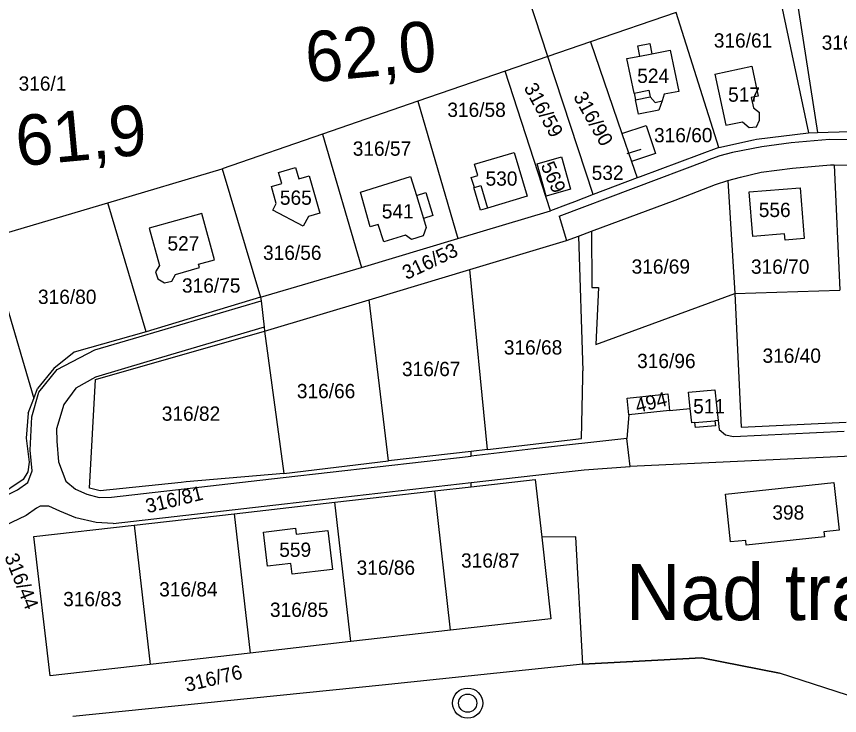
# Model space of a CAD drawing. Extents: x -805826 to -803822, y -1165880 to -1164382.
# Drawn here: x -805597.3 to -805401.4, y -1164887.3 to -1164720.9 of the extents above; entities that cross this region are included whole.
import ezdxf

# ---------------------------------------------------------------- set-up
doc = ezdxf.new("R2010")
doc.units = 0
for name, color, linetype in [('kilometráž - 2880', 7, 'Continuous'), ('kn_celek - Cisla parcel pomocna', 7, 'Continuous'), ('kn_celek - Cisla pozemkovych parcel', 7, 'Continuous'), ('kn_celek - Cisla stavebnich parcel', 7, 'Continuous'), ('kn_celek - Dalsi prvky mapy popis', 7, 'Continuous'), ('kn_celek - Hranice parcel', 7, 'Continuous'), ('kn_celek - Vnitrni kresby', 7, 'Continuous'), ('plochy - SZDC', 7, 'Continuous')]:
    doc.layers.add(name, color=color, linetype=linetype)

msp = doc.modelspace()

# ---------------------------------------------------------------- linework, layer by layer
at = {"layer": 'kilometráž - 2880'}
for radius in [3.59, 2.17]:
    msp.add_circle((-805489.96, -1164884.32), radius, dxfattribs=at)
at = {"layer": 'kn_celek - Cisla parcel pomocna'}
msp.add_line((-805448.76, -1164752.55), (-805452.11, -1164753.57), dxfattribs=at)
at = {"layer": 'kn_celek - Hranice parcel'}
for p, q in [((-805416.61, -1164711.68), (-805408.85, -1164748.58)), ((-805412.4, -1164711.49), (-805406.69, -1164748.5)), ((-805470.84, -1164730.39), (-805476.69, -1164712.54)), ((-805440.33, -1164719.92), (-805460.68, -1164726.9)), ((-805430.19, -1164752.06), (-805440.33, -1164719.92)), ((-805460.68, -1164726.9), (-805470.84, -1164730.39)), ((-805460.68, -1164726.9), (-805453.24, -1164748.73)), ((-805449.44, -1164727.87), (-805446.59, -1164727.32)), ((-805448.96, -1164730.29), (-805449.44, -1164727.87)), ((-805446.59, -1164727.32), (-805446.13, -1164729.74)), ((-805446.13, -1164729.74), (-805441.77, -1164728.9)), ((-805441.77, -1164728.9), (-805439.69, -1164738.68)), ((-805470.84, -1164730.39), (-805481.02, -1164733.9)), ((-805460.07, -1164763.25), (-805470.84, -1164730.39)), ((-805452.08, -1164730.89), (-805448.96, -1164730.29)), ((-805450.33, -1164739.12), (-805452.08, -1164730.89)), ((-805431.14, -1164734.58), (-805422.33, -1164732.66)), ((-805422.33, -1164732.66), (-805420.78, -1164739.8)), ((-805481.02, -1164733.9), (-805501.84, -1164741.04)), ((-805470.22, -1164767.14), (-805481.02, -1164733.9)), ((-805431.14, -1164734.58), (-805428.49, -1164746.77)), ((-805450.33, -1164739.12), (-805449.97, -1164740.67)), ((-805443.15, -1164739.38), (-805443.69, -1164740.97)), ((-805439.69, -1164738.68), (-805443.15, -1164739.38)), ((-805501.84, -1164741.04), (-805524.52, -1164748.85)), ((-805501.84, -1164741.04), (-805492.26, -1164773.73)), ((-805449.26, -1164744.09), (-805449.97, -1164740.67)), ((-805443.69, -1164740.97), (-805444.47, -1164743.17)), ((-805420.78, -1164739.8), (-805422.45, -1164740.16)), ((-805422.45, -1164740.16), (-805421.92, -1164742.61)), ((-805444.47, -1164743.17), (-805449.26, -1164744.09)), ((-805421.92, -1164742.61), (-805420.49, -1164743.71)), ((-805421.19, -1164747.14), (-805420.48, -1164745.54)), ((-805420.48, -1164745.54), (-805420.49, -1164743.71)), ((-805453.24, -1164748.73), (-805447.49, -1164746.83)), ((-805447.49, -1164746.83), (-805445.28, -1164753.47)), ((-805428.49, -1164746.77), (-805424.53, -1164745.97)), ((-805424.53, -1164745.97), (-805422.96, -1164747.27)), ((-805422.96, -1164747.27), (-805421.19, -1164747.14)), ((-805524.52, -1164748.85), (-805548.34, -1164757.09)), ((-805524.52, -1164748.85), (-805515.24, -1164780.59)), ((-805453.24, -1164748.73), (-805450.98, -1164755.36)), ((-805421.18, -1164750.08), (-805408.85, -1164748.58)), ((-805408.85, -1164748.58), (-805406.69, -1164748.5)), ((-805406.69, -1164748.5), (-805398.97, -1164748.23)), ((-805430.19, -1164752.06), (-805421.93, -1164750.23)), ((-805421.93, -1164750.23), (-805421.18, -1164750.08)), ((-805412.93, -1164750.97), (-805419.97, -1164751.89)), ((-805403.85, -1164750.15), (-805412.93, -1164750.97)), ((-805398.74, -1164750.19), (-805403.85, -1164750.15)), ((-805488.36, -1164756.04), (-805478.91, -1164753.21)), ((-805478.91, -1164753.21), (-805475.77, -1164763.65)), ((-805430.19, -1164752.06), (-805448.92, -1164759)), ((-805426.96, -1164753.24), (-805429.9, -1164754.04)), ((-805419.97, -1164751.89), (-805426.96, -1164753.24)), ((-805473.43, -1164755.93), (-805467.65, -1164754.27)), ((-805468.15, -1164768.4), (-805432.78, -1164755.06)), ((-805467.65, -1164754.27), (-805465.46, -1164761.98)), ((-805445.28, -1164753.47), (-805450.98, -1164755.36)), ((-805429.9, -1164754.04), (-805432.78, -1164755.06)), ((-805575.61, -1164765.21), (-805548.34, -1164757.09)), ((-805548.34, -1164757.09), (-805539.22, -1164787.71)), ((-805534.98, -1164757.98), (-805530.93, -1164756.81)), ((-805530.93, -1164756.81), (-805530.16, -1164759.48)), ((-805487.56, -1164758.75), (-805488.36, -1164756.04)), ((-805471.23, -1164763.63), (-805473.43, -1164755.93)), ((-805450.98, -1164755.36), (-805449.65, -1164759.26)), ((-805420.07, -1164757.92), (-805412.65, -1164757)), ((-805412.65, -1164757), (-805403.6, -1164756.17)), ((-805403.6, -1164756.17), (-805402.75, -1164756.18)), ((-805402.75, -1164756.18), (-805398.55, -1164756.29)), ((-805402.75, -1164756.18), (-805401.35, -1164786.02)), ((-805534.2, -1164760.64), (-805534.98, -1164757.98)), ((-805530.16, -1164759.48), (-805527.71, -1164758.78)), ((-805527.71, -1164758.78), (-805525.15, -1164767.7)), ((-805515.49, -1164762.68), (-805503.54, -1164758.93)), ((-805503.54, -1164758.93), (-805502.16, -1164763.45)), ((-805489.1, -1164759.2), (-805487.56, -1164758.75)), ((-805488.36, -1164761.57), (-805489.1, -1164759.2)), ((-805449.65, -1164759.26), (-805460.07, -1164763.25)), ((-805448.92, -1164759), (-805449.65, -1164759.26)), ((-805428.01, -1164759.91), (-805425, -1164759.11)), ((-805425, -1164759.11), (-805420.07, -1164757.92)), ((-805536.65, -1164761.34), (-805534.2, -1164760.64)), ((-805433.83, -1164761.97), (-805430.96, -1164760.88)), ((-805430.96, -1164760.88), (-805428.01, -1164759.91)), ((-805428.01, -1164759.91), (-805426.34, -1164786.82)), ((-805535.49, -1164765.38), (-805536.65, -1164761.34)), ((-805513.12, -1164770.95), (-805515.49, -1164762.68)), ((-805502.16, -1164763.45), (-805499.87, -1164762.74)), ((-805499.87, -1164762.74), (-805498.28, -1164768.26)), ((-805488.48, -1164761.6), (-805488.36, -1164761.57)), ((-805486.88, -1164766.95), (-805488.48, -1164761.6)), ((-805465.46, -1164761.98), (-805471.23, -1164763.63)), ((-805440.6, -1164764.55), (-805436.72, -1164763.1)), ((-805436.72, -1164763.1), (-805433.83, -1164761.97)), ((-805422.94, -1164762.62), (-805410.81, -1164761.63)), ((-805422.07, -1164773.22), (-805422.94, -1164762.62)), ((-805410.81, -1164761.63), (-805409.85, -1164773.75)), ((-805475.77, -1164763.65), (-805485.25, -1164766.46)), ((-805464.51, -1164764.95), (-805466.03, -1164765.53)), ((-805460.07, -1164763.25), (-805464.51, -1164764.95)), ((-805460.52, -1164771.98), (-805440.6, -1164764.55)), ((-805604.38, -1164773.78), (-805575.61, -1164765.21)), ((-805566.47, -1164795.9), (-805575.61, -1164765.21)), ((-805536.34, -1164766.94), (-805535.49, -1164765.38)), ((-805529.1, -1164770.75), (-805536.34, -1164766.94)), ((-805485.25, -1164766.46), (-805486.88, -1164766.95)), ((-805466.03, -1164765.53), (-805470.22, -1164767.14)), ((-805553.23, -1164767.75), (-805565.77, -1164771.25)), ((-805550.17, -1164778.77), (-805553.23, -1164767.75)), ((-805527.87, -1164768.49), (-805529.1, -1164770.75)), ((-805525.15, -1164767.7), (-805527.87, -1164768.49)), ((-805498.28, -1164768.26), (-805500.47, -1164768.94)), ((-805500.47, -1164768.94), (-805499.8, -1164771.12)), ((-805492.26, -1164773.73), (-805470.22, -1164767.14)), ((-805468.15, -1164768.4), (-805466.43, -1164774.19)), ((-805511.22, -1164770.38), (-805513.12, -1164770.95)), ((-805509.93, -1164774.52), (-805511.22, -1164770.38)), ((-805565.77, -1164771.25), (-805563.3, -1164780.13)), ((-805504.75, -1164772.9), (-805509.93, -1164774.52)), ((-805503.3, -1164773.95), (-805504.75, -1164772.9)), ((-805499.8, -1164771.12), (-805500.57, -1164773.09)), ((-805463.61, -1164773.14), (-805460.52, -1164771.98)), ((-805460.52, -1164771.98), (-805460.37, -1164784.97)), ((-805414.52, -1164772.62), (-805422.07, -1164773.22)), ((-805414.39, -1164774.11), (-805414.52, -1164772.62)), ((-805604.38, -1164773.78), (-805593.22, -1164811.82)), ((-805515.24, -1164780.59), (-805492.26, -1164773.73)), ((-805500.57, -1164773.09), (-805503.3, -1164773.95)), ((-805489.44, -1164781.07), (-805466.43, -1164774.19)), ((-805466.43, -1164774.19), (-805463.61, -1164773.14)), ((-805463.61, -1164773.14), (-805462.53, -1164805.18)), ((-805409.85, -1164773.75), (-805414.39, -1164774.11)), ((-805554.04, -1164779.84), (-805550.17, -1164778.77)), ((-805563.3, -1164780.13), (-805564.26, -1164781.62)), ((-805559.52, -1164782.26), (-805553.81, -1164780.65)), ((-805553.81, -1164780.65), (-805554.04, -1164779.84)), ((-805539.22, -1164787.71), (-805515.24, -1164780.59)), ((-805564.26, -1164781.62), (-805563.7, -1164783.35)), ((-805560.38, -1164783.84), (-805559.52, -1164782.26)), ((-805513.36, -1164788.3), (-805489.44, -1164781.07)), ((-805485.2, -1164823.93), (-805489.44, -1164781.07)), ((-805563.7, -1164783.35), (-805562.14, -1164784.24)), ((-805562.14, -1164784.24), (-805560.38, -1164783.84)), ((-805460.37, -1164784.97), (-805460.37, -1164785.38)), ((-805460.37, -1164785.38), (-805458.81, -1164785.4)), ((-805458.81, -1164785.4), (-805459.43, -1164798.91)), ((-805426.34, -1164786.82), (-805401.35, -1164786.02)), ((-805539.22, -1164787.71), (-805566.47, -1164795.9)), ((-805539.22, -1164787.71), (-805539.12, -1164788.58)), ((-805539.12, -1164788.58), (-805538.38, -1164794.81)), ((-805538.27, -1164795.8), (-805513.36, -1164788.3)), ((-805508.83, -1164826.67), (-805513.36, -1164788.3)), ((-805459.43, -1164798.91), (-805426.34, -1164786.82)), ((-805426.34, -1164786.82), (-805424.87, -1164818.65)), ((-805566.47, -1164795.9), (-805583.61, -1164800.8)), ((-805578.54, -1164807.27), (-805538.27, -1164795.8)), ((-805538.38, -1164794.81), (-805538.27, -1164795.8)), ((-805538.27, -1164795.8), (-805533.7, -1164829.62)), ((-805583.61, -1164800.8), (-805588.43, -1164804.66)), ((-805588.43, -1164804.66), (-805592.31, -1164809.45)), ((-805462.56, -1164806.78), (-805462.53, -1164805.18)), ((-805579.93, -1164833.18), (-805578.54, -1164807.27)), ((-805462.88, -1164821.36), (-805462.56, -1164806.78)), ((-805593.22, -1164811.82), (-805592.31, -1164809.45)), ((-805437.4, -1164810.31), (-805431.13, -1164809.74)), ((-805431.13, -1164809.74), (-805430.33, -1164817)), ((-805594.53, -1164815.28), (-805593.22, -1164811.82)), ((-805452.01, -1164811.73), (-805442.32, -1164810.72)), ((-805451.63, -1164815.7), (-805452.01, -1164811.73)), ((-805442.32, -1164810.72), (-805441.91, -1164814.69)), ((-805436.99, -1164814.18), (-805437.4, -1164810.31)), ((-805594.53, -1164815.28), (-805595.06, -1164821.26)), ((-805451.63, -1164815.7), (-805452.05, -1164821.31)), ((-805441.91, -1164814.69), (-805451.63, -1164815.7)), ((-805441.91, -1164814.69), (-805436.99, -1164814.18)), ((-805436.63, -1164817.61), (-805436.99, -1164814.18)), ((-805435.86, -1164817.54), (-805436.63, -1164817.61)), ((-805435.72, -1164818.72), (-805435.86, -1164817.54)), ((-805430.33, -1164817), (-805431.09, -1164817.08)), ((-805431.09, -1164817.08), (-805430.95, -1164818.29)), ((-805430.33, -1164817), (-805430.08, -1164819.17)), ((-805424.87, -1164818.65), (-805399.9, -1164817.43)), ((-805430.95, -1164818.29), (-805435.72, -1164818.72)), ((-805430.08, -1164819.17), (-805428.62, -1164820.47)), ((-805426.66, -1164820.85), (-805400.32, -1164819.59)), ((-805595.06, -1164821.26), (-805594.34, -1164826.99)), ((-805485.2, -1164823.93), (-805462.88, -1164821.36)), ((-805452.05, -1164821.31), (-805474.31, -1164823.82)), ((-805451.24, -1164827.98), (-805452.05, -1164821.31)), ((-805428.62, -1164820.47), (-805426.66, -1164820.85)), ((-805474.31, -1164823.82), (-805489.13, -1164825.51)), ((-805489.13, -1164824.38), (-805508.83, -1164826.67)), ((-805485.2, -1164823.93), (-805489.13, -1164824.38)), ((-805489.13, -1164825.51), (-805489.13, -1164824.38)), ((-805387.37, -1164825.01), (-805451.24, -1164827.98)), ((-805594.34, -1164826.99), (-805594.59, -1164829.23)), ((-805533.7, -1164829.62), (-805508.83, -1164826.67)), ((-805594.59, -1164829.23), (-805595.74, -1164831.06)), ((-805533.7, -1164829.62), (-805556.93, -1164831.67)), ((-805473.7, -1164830.04), (-805462.19, -1164828.76)), ((-805462.19, -1164828.76), (-805451.24, -1164827.98)), ((-805595.74, -1164831.06), (-805603.81, -1164836.55)), ((-805556.93, -1164831.67), (-805558.14, -1164831.8)), ((-805489.12, -1164831.81), (-805473.7, -1164830.04)), ((-805489.12, -1164832.82), (-805473.9, -1164831.06)), ((-805473.9, -1164831.06), (-805472.33, -1164844.82)), ((-805577.38, -1164833.81), (-805579.93, -1164833.18)), ((-805558.14, -1164831.8), (-805577.38, -1164833.81)), ((-805533.58, -1164836.89), (-805489.12, -1164831.81)), ((-805497.76, -1164833.82), (-805489.12, -1164832.82)), ((-805489.12, -1164832.82), (-805489.12, -1164831.81)), ((-805428.57, -1164834.57), (-805402.84, -1164831.8)), ((-805402.84, -1164831.8), (-805401.53, -1164843.13)), ((-805521.58, -1164836.51), (-805497.76, -1164833.82)), ((-805494, -1164866.97), (-805497.76, -1164833.82)), ((-805427.38, -1164845.91), (-805428.57, -1164834.57)), ((-805591.68, -1164837.46), (-805592.55, -1164837.88)), ((-805589.65, -1164837.41), (-805591.68, -1164837.46)), ((-805587, -1164838.65), (-805589.65, -1164837.41)), ((-805574.34, -1164841.56), (-805533.58, -1164836.89)), ((-805545.49, -1164839.24), (-805521.58, -1164836.51)), ((-805517.73, -1164869.63), (-805521.58, -1164836.51)), ((-805592.55, -1164837.88), (-805595.02, -1164839.63)), ((-805583.24, -1164840.2), (-805587, -1164838.65)), ((-805569.35, -1164841.95), (-805545.49, -1164839.24)), ((-805545.49, -1164839.24), (-805541.69, -1164872.4)), ((-805595.02, -1164839.63), (-805602.1, -1164843.02)), ((-805578.39, -1164841.35), (-805583.24, -1164840.2)), ((-805574.34, -1164841.56), (-805578.39, -1164841.35)), ((-805593.16, -1164844.68), (-805569.35, -1164841.95)), ((-805569.35, -1164841.95), (-805565.55, -1164875.1)), ((-805538.51, -1164843.59), (-805530.92, -1164842.7)), ((-805530.92, -1164842.7), (-805530.76, -1164844.1)), ((-805530.76, -1164844.1), (-805523.23, -1164843.2)), ((-805523.23, -1164843.2), (-805522.13, -1164852.49)), ((-805401.53, -1164843.13), (-805405.15, -1164843.52)), ((-805589.35, -1164877.84), (-805593.16, -1164844.68)), ((-805537.55, -1164851.72), (-805538.51, -1164843.59)), ((-805464.19, -1164844.7), (-805472.33, -1164844.82)), ((-805472.33, -1164844.82), (-805470.12, -1164864.24)), ((-805462.52, -1164875.08), (-805464.19, -1164844.7)), ((-805405.03, -1164844.71), (-805423.65, -1164846.74)), ((-805405.15, -1164843.52), (-805405.03, -1164844.71)), ((-805423.79, -1164845.57), (-805427.38, -1164845.91)), ((-805423.65, -1164846.74), (-805423.79, -1164845.57)), ((-805532.02, -1164851.07), (-805537.55, -1164851.72)), ((-805531.7, -1164853.65), (-805532.02, -1164851.07)), ((-805522.13, -1164852.49), (-805531.7, -1164853.65)), ((-805470.12, -1164864.24), (-805494, -1164866.97)), ((-805494, -1164866.97), (-805517.73, -1164869.63)), ((-805517.73, -1164869.63), (-805541.69, -1164872.4)), ((-805541.69, -1164872.4), (-805565.55, -1164875.1)), ((-805462.52, -1164875.08), (-805434.29, -1164873.57)), ((-805434.29, -1164873.57), (-805415.73, -1164877.21)), ((-805565.55, -1164875.1), (-805589.35, -1164877.84)), ((-805462.52, -1164875.08), (-805510.27, -1164880.08)), ((-805384.69, -1164887.2), (-805415.73, -1164877.21)), ((-805510.27, -1164880.08), (-805583.88, -1164887.5))]:
    msp.add_line(p, q, dxfattribs=at)
at = {"layer": 'kn_celek - Vnitrni kresby'}
for p, q in [((-805448.96, -1164730.29), (-805446.13, -1164729.74)), ((-805450.33, -1164739.12), (-805446.84, -1164738.38)), ((-805446.84, -1164738.38), (-805446.51, -1164740)), ((-805449.97, -1164740.67), (-805446.51, -1164740)), ((-805446.51, -1164740), (-805445.36, -1164741.32)), ((-805445.36, -1164741.32), (-805443.69, -1164740.97)), ((-805488.36, -1164761.57), (-805486.85, -1164761.12)), ((-805486.85, -1164761.12), (-805485.25, -1164766.46)), ((-805502.16, -1164763.45), (-805500.47, -1164768.94)), ((-805568.15, -1164797.12), (-805539.12, -1164788.58)), ((-805538.38, -1164794.81), (-805566.33, -1164803.07)), ((-805578.67, -1164800.25), (-805568.15, -1164797.12)), ((-805587.68, -1164804.92), (-805578.67, -1164800.25)), ((-805566.33, -1164803.07), (-805578.52, -1164806.74)), ((-805591.98, -1164810.31), (-805587.68, -1164804.92)), ((-805578.52, -1164806.74), (-805583.17, -1164809.31)), ((-805583.17, -1164809.31), (-805586.04, -1164813.21)), ((-805593.67, -1164816.2), (-805591.98, -1164810.31)), ((-805586.04, -1164813.21), (-805587.8, -1164819.01)), ((-805594.07, -1164824.13), (-805593.67, -1164816.2)), ((-805435.86, -1164817.54), (-805431.09, -1164817.08)), ((-805587.8, -1164819.01), (-805587.76, -1164821.93)), ((-805587.76, -1164821.93), (-805587.34, -1164826.9)), ((-805593.6, -1164829.06), (-805594.07, -1164824.13)), ((-805533.88, -1164830.58), (-805489.13, -1164825.51)), ((-805587.34, -1164826.9), (-805585.58, -1164831.46)), ((-805594.65, -1164831.81), (-805593.6, -1164829.06)), ((-805585.58, -1164831.46), (-805583.3, -1164833.4)), ((-805574.68, -1164835.3), (-805533.88, -1164830.58)), ((-805602.11, -1164836.05), (-805597.07, -1164833.55)), ((-805597.07, -1164833.55), (-805594.65, -1164831.81)), ((-805583.3, -1164833.4), (-805580.55, -1164834.54)), ((-805580.55, -1164834.54), (-805577.69, -1164835.33)), ((-805577.69, -1164835.33), (-805574.68, -1164835.3))]:
    msp.add_line(p, q, dxfattribs=at)
at = {"layer": 'plochy - SZDC'}
for p, q in [((-805434.29, -1164873.57), (-805462.52, -1164875.08)), ((-805415.73, -1164877.21), (-805434.29, -1164873.57)), ((-805462.52, -1164875.08), (-805510.27, -1164880.08)), ((-805384.69, -1164887.2), (-805415.73, -1164877.21)), ((-805510.27, -1164880.08), (-805583.88, -1164887.5))]:
    msp.add_line(p, q, dxfattribs=at)

# ---------------------------------------------------------------- texts
at = {"layer": 'kilometráž - 2880'}
for s, rotation, p in [('62,0', 5.3684, (-805528.04, -1164736.63)), ('61,9', 5.3097, (-805597.01, -1164756.54))]:
    msp.add_text(s, height=12, rotation=rotation, dxfattribs=at).set_placement(p)
at = {"layer": 'kn_celek - Cisla parcel pomocna'}
msp.add_text('532', height=3.4, dxfattribs=at).set_placement((-805460.44, -1164759.77))
msp.add_text('316/44', height=3.4, rotation=291.807, dxfattribs=at).set_placement((-805600.26, -1164849.46))
at = {"layer": 'kn_celek - Cisla pozemkovych parcel'}
for s, p in [('316/61', (-805431.37, -1164728.27)), ('316/62', (-805405.69, -1164728.77)), ('316/1', (-805596.83, -1164738.52)), ('316/58', (-805494.79, -1164744.77)), ('316/60', (-805445.6, -1164750.81)), ('316/57', (-805517.3, -1164754.01)), ('316/56', (-805538.65, -1164778.8)), ('316/69', (-805450.94, -1164782.08)), ('316/70', (-805422.53, -1164782.11)), ('316/75', (-805557.94, -1164786.6)), ('316/80', (-805592.21, -1164789.29)), ('316/68', (-805481.34, -1164801.33)), ('316/40', (-805419.78, -1164803.3)), ('316/96', (-805449.62, -1164804.56)), ('316/67', (-805505.58, -1164806.47)), ('316/66', (-805530.6, -1164811.73)), ('316/82', (-805562.75, -1164817.1)), ('316/87', (-805491.52, -1164852.07)), ('316/86', (-805516.38, -1164853.76)), ('316/84', (-805563.37, -1164858.92)), ('316/83', (-805586.22, -1164861.24)), ('316/85', (-805537.01, -1164863.79))]:
    msp.add_text(s, height=3.4, dxfattribs=at).set_placement(p)
for s, rotation, p in [('316/59', 298.566, (-805476.69, -1164737.79)), ('316/90', 299.259, (-805464.92, -1164739.93)), ('316/53', 25.326, (-805504.5, -1164783.62)), ('316/81', 13.869, (-805566.14, -1164839.15)), ('316/76', 13.464, (-805556.84, -1164881.67))]:
    msp.add_text(s, height=3.4, rotation=rotation, dxfattribs=at).set_placement(p)
at = {"layer": 'kn_celek - Cisla stavebnich parcel'}
for s, height, p in [('524', 3.4, (-805449.6, -1164736.68)), ('517', 3.4, (-805427.97, -1164741.15)), ('532', 0.005, (-805448.76, -1164752.55)), ('530', 3.4, (-805485.69, -1164761.14)), ('565', 3.4, (-805534.64, -1164765.69)), ('541', 3.4, (-805510.39, -1164768.94)), ('556', 3.4, (-805420.67, -1164768.6)), ('527', 3.4, (-805561.4, -1164776.57)), ('511', 3.4, (-805436.29, -1164815.36)), ('398', 3.4, (-805417.44, -1164840.64)), ('559', 3.4, (-805534.79, -1164849.5))]:
    msp.add_text(s, height=height, dxfattribs=at).set_placement(p)
for s, rotation, p in [('569', 293.868, (-805472.63, -1164756.31)), ('494', 13.923, (-805449.59, -1164815.28))]:
    msp.add_text(s, height=3.4, rotation=rotation, dxfattribs=at).set_placement(p)
at = {"layer": 'kn_celek - Dalsi prvky mapy popis'}
msp.add_text('Nad tratí', height=13.4, dxfattribs=at).set_placement((-805452.28, -1164864.57))

doc.saveas('drawing.dxf')
